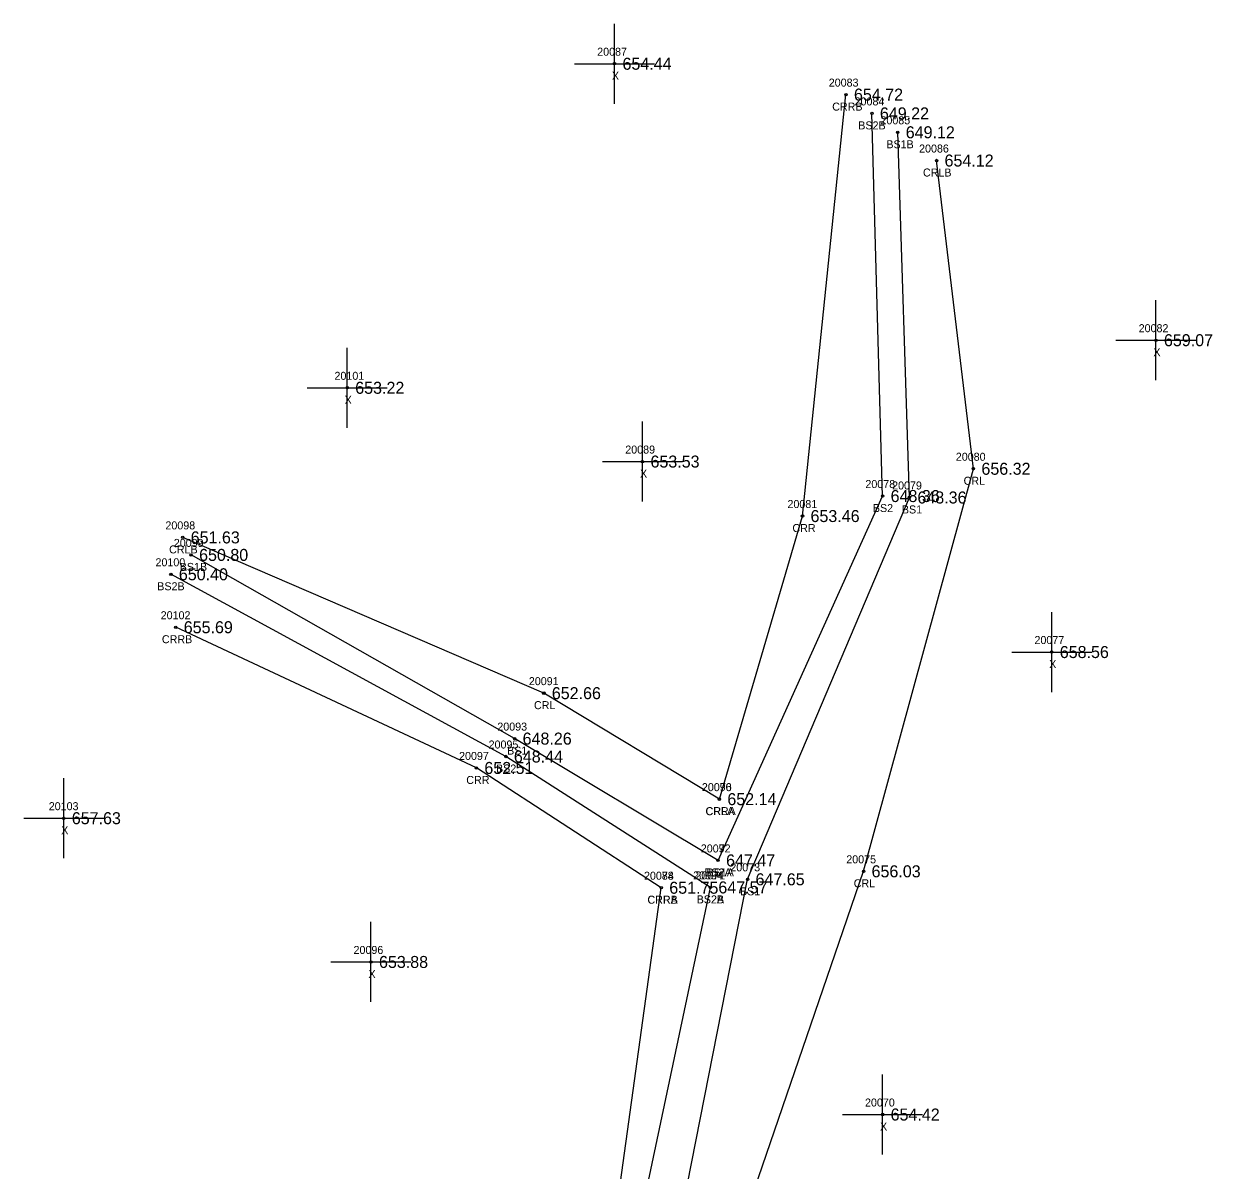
# Model space of a CAD drawing. Extents: x 1655675 to 1657082, y 1004080 to 1005193.
# Drawn here: x 1656323.4 to 1656471.9, y 1005049.5 to 1005192.8 of the extents above; entities that cross this region are included whole.
import ezdxf

# ---------------------------------------------------------------- set-up
doc = ezdxf.new("R2010")
doc.units = 0
for name, color, linetype in [('RD_DTM_BkLn2', 7, 'Continuous'), ('RD_DTM_BkLn_txCode', 7, 'Continuous'), ('RD_EX_H2O', 7, 'Continuous'), ('RD_EX_H2O_txCode', 7, 'Continuous'), ('RD_EX_Misc', 7, 'Continuous'), ('RD_EX_Misc_txCode', 7, 'Continuous'), ('RD_EX_TX_H2O_ELEV', 7, 'Continuous'), ('RD_EX_TX_Misc_ELEV', 7, 'Continuous'), ('RD_SMD_Locator', 7, 'Continuous')]:
    doc.layers.add(name, color=color, linetype=linetype)

msp = doc.modelspace()

# ---------------------------------------------------------------- linework, layer by layer
at = {"layer": 'RD_DTM_BkLn2'}
for points in [[(1656410.19, 1005088.26), (1656430.75, 1005133.81), (1656429.41, 1005181.64)], [(1656390.72, 1004627.52), (1656382.97, 1004639.34), (1656373.07, 1004660.2), (1656376.96, 1004698.66), (1656386.88, 1004718.9), (1656381.04, 1004756.9), (1656388.26, 1004792), (1656390.04, 1004832.88), (1656413.02, 1004880.46), (1656422.17, 1004937.24), (1656409.91, 1004961.28), (1656410.07, 1005007.08), (1656404.22, 1005036.82), (1656413.87, 1005085.9), (1656434.1, 1005133.63), (1656432.64, 1005179.28)], [(1656410.19, 1005088.26), (1656384.76, 1005103.49), (1656344.33, 1005126.45)], [(1656409.22, 1005084.89), (1656383.67, 1005101.25), (1656341.8, 1005124.03)], [(1656378.15, 1004634.61), (1656371.17, 1004659.81), (1656372.69, 1004701.15), (1656384.23, 1004720.35), (1656377.68, 1004756.93), (1656385.56, 1004794.36), (1656385.16, 1004833.8), (1656408.06, 1004879.84), (1656418.86, 1004937.52), (1656406.15, 1004960.8), (1656407.08, 1005007.2), (1656399.18, 1005037.18), (1656409.22, 1005084.89)]]:
    msp.add_lwpolyline(points, dxfattribs=at)
at = {"layer": 'RD_EX_H2O'}
for points in [[(1656410.35, 1005095.92), (1656420.74, 1005131.31), (1656426.17, 1005183.99)], [(1656396.09, 1004633.07), (1656383.79, 1004647.24), (1656376.78, 1004660.97), (1656381.31, 1004695.03), (1656390.77, 1004716.64), (1656386.6, 1004756.66), (1656392.47, 1004790.44), (1656395.46, 1004834.73), (1656418.17, 1004880.53), (1656428.48, 1004936.46), (1656416.99, 1004968.14), (1656420.24, 1005011.82), (1656412.2, 1005039.74), (1656428.37, 1005086.9), (1656442.1, 1005137.22), (1656437.49, 1005175.75)], [(1656410.35, 1005095.92), (1656388.41, 1005109.17), (1656343.28, 1005128.64)], [(1656403.09, 1005084.85), (1656379.98, 1005099.82), (1656342.41, 1005117.41)], [(1656368.16, 1004641.29), (1656363.88, 1004666), (1656364.85, 1004699.99), (1656373.08, 1004726.71), (1656370.55, 1004754.49), (1656376.9, 1004793.18), (1656381.94, 1004832.3), (1656396.67, 1004890.43), (1656408.46, 1004936.92), (1656401.87, 1004961.79), (1656402.89, 1005007.98), (1656396.57, 1005037.78), (1656403.09, 1005084.85)]]:
    msp.add_lwpolyline(points, dxfattribs=at)
at = {"layer": 'RD_EX_Misc'}
for p, q in [((1656397.24, 1005182.85), (1656397.24, 1005192.85)), ((1656392.24, 1005187.85), (1656402.24, 1005187.85)), ((1656464.91, 1005148.29), (1656464.91, 1005158.29)), ((1656363.84, 1005142.34), (1656363.84, 1005152.34)), ((1656459.91, 1005153.29), (1656469.91, 1005153.29)), ((1656358.84, 1005147.34), (1656368.84, 1005147.34)), ((1656400.74, 1005133.12), (1656400.74, 1005143.12)), ((1656395.74, 1005138.12), (1656405.74, 1005138.12)), ((1656451.89, 1005109.31), (1656451.89, 1005119.31)), ((1656446.89, 1005114.31), (1656456.89, 1005114.31)), ((1656328.42, 1005088.54), (1656328.42, 1005098.54)), ((1656323.42, 1005093.54), (1656333.42, 1005093.54)), ((1656366.81, 1005070.57), (1656366.81, 1005080.57)), ((1656361.81, 1005075.57), (1656371.81, 1005075.57)), ((1656430.75, 1005051.5), (1656430.75, 1005061.5)), ((1656425.75, 1005056.5), (1656435.75, 1005056.5))]:
    msp.add_line(p, q, dxfattribs=at)
at = {"layer": 'RD_SMD_Locator'}
for centre in [(1656397.24, 1005187.85), (1656426.17, 1005183.99), (1656429.41, 1005181.64), (1656432.64, 1005179.28), (1656437.49, 1005175.75), (1656464.91, 1005153.29), (1656363.84, 1005147.34), (1656400.74, 1005138.12), (1656442.1, 1005137.22), (1656430.75, 1005133.81), (1656434.1, 1005133.63), (1656420.74, 1005131.31), (1656343.28, 1005128.64), (1656344.33, 1005126.45), (1656341.8, 1005124.03), (1656342.41, 1005117.41), (1656451.89, 1005114.31), (1656388.41, 1005109.17), (1656384.76, 1005103.49), (1656383.67, 1005101.25), (1656379.98, 1005099.82), (1656410.35, 1005095.92), (1656410.35, 1005095.92), (1656328.42, 1005093.54), (1656410.19, 1005088.26), (1656410.19, 1005088.26), (1656428.37, 1005086.9), (1656413.87, 1005085.9), (1656403.09, 1005084.85), (1656403.09, 1005084.85), (1656409.22, 1005084.89), (1656409.22, 1005084.89), (1656366.81, 1005075.57), (1656430.75, 1005056.5)]:
    msp.add_circle(centre, 0.15, dxfattribs=at)

# ---------------------------------------------------------------- texts
at = {"layer": 'RD_DTM_BkLn_txCode'}
for s, p in [('20084', (1656427.25, 1005182.64)), ('BS2B', (1656427.71, 1005179.64)), ('20085', (1656430.48, 1005180.28)), ('BS1B', (1656431.22, 1005177.28)), ('20078', (1656428.6, 1005134.81)), ('20079', (1656431.94, 1005134.63)), ('BS2', (1656429.53, 1005131.81)), ('BS1', (1656433.16, 1005131.63)), ('20099', (1656342.17, 1005127.45)), ('20100', (1656339.88, 1005125.03)), ('BS1B', (1656342.91, 1005124.45)), ('BS2B', (1656340.1, 1005122.03)), ('20093', (1656382.6, 1005104.49)), ('20095', (1656381.51, 1005102.25)), ('BS1', (1656383.82, 1005101.49)), ('BS2', (1656382.44, 1005099.25)), ('20072', (1656408.03, 1005089.26)), ('20092', (1656408.03, 1005089.26)), ('20094', (1656407.07, 1005085.89)), ('20071', (1656407.35, 1005085.89)), ('BS2A', (1656408.47, 1005086.26)), ('BS1A', (1656408.75, 1005086.26)), ('20073', (1656411.72, 1005086.9)), ('BS2A', (1656407.51, 1005082.89)), ('BS2B', (1656407.52, 1005082.89)), ('BS1', (1656412.93, 1005083.9))]:
    msp.add_text(s, height=1, dxfattribs=at).set_placement(p)
at = {"layer": 'RD_EX_H2O_txCode'}
for s, p in [('20083', (1656424.02, 1005184.99)), ('CRRB', (1656424.45, 1005181.99)), ('20086', (1656435.31, 1005176.75)), ('CRLB', (1656435.79, 1005173.75)), ('20080', (1656439.9, 1005138.22)), ('CRL', (1656440.87, 1005135.22)), ('20081', (1656418.86, 1005132.31)), ('20098', (1656341.12, 1005129.64)), ('CRR', (1656419.48, 1005129.31)), ('CRLB', (1656341.58, 1005126.64)), ('20102', (1656340.53, 1005118.41)), ('CRRB', (1656340.68, 1005115.41)), ('20091', (1656386.54, 1005110.17)), ('CRL', (1656387.18, 1005107.17)), ('20097', (1656377.82, 1005100.82)), ('CRR', (1656378.72, 1005097.82)), ('20090', (1656408.16, 1005096.92)), ('20076', (1656408.17, 1005096.92)), ('CRRA', (1656408.61, 1005093.92)), ('CRLA', (1656408.64, 1005093.92)), ('20075', (1656426.21, 1005087.9)), ('20074', (1656400.93, 1005085.85)), ('20088', (1656400.93, 1005085.85)), ('CRL', (1656427.14, 1005084.9)), ('CRRA', (1656401.35, 1005082.85)), ('CRRB', (1656401.37, 1005082.85))]:
    msp.add_text(s, height=1, dxfattribs=at).set_placement(p)
at = {"layer": 'RD_EX_Misc_txCode'}
for s, p in [('20087', (1656395.08, 1005188.85)), ('X', (1656396.92, 1005185.85)), ('20082', (1656462.75, 1005154.29)), ('X', (1656464.59, 1005151.29)), ('20101', (1656362.25, 1005148.34)), ('X', (1656363.52, 1005145.34)), ('20089', (1656398.59, 1005139.12)), ('X', (1656400.43, 1005136.12)), ('20077', (1656449.73, 1005115.31)), ('X', (1656451.57, 1005112.31)), ('20103', (1656326.54, 1005094.54)), ('X', (1656328.1, 1005091.54)), ('20096', (1656364.63, 1005076.57)), ('X', (1656366.5, 1005073.57)), ('20070', (1656428.55, 1005057.5)), ('X', (1656430.43, 1005054.5))]:
    msp.add_text(s, height=1, dxfattribs=at).set_placement(p)
at = {"layer": 'RD_EX_TX_H2O_ELEV'}
for s, p in [('654.72', (1656427.17, 1005183.24)), ('654.12', (1656438.49, 1005175)), ('656.32', (1656443.1, 1005136.47)), ('653.46', (1656421.74, 1005130.56)), ('651.63', (1656344.28, 1005127.89)), ('655.69', (1656343.41, 1005116.66)), ('652.66', (1656389.41, 1005108.42)), ('652.51', (1656380.98, 1005099.07)), ('652.14', (1656411.35, 1005095.17)), ('652.14', (1656411.35, 1005095.17)), ('656.03', (1656429.37, 1005086.15)), ('651.75', (1656404.09, 1005084.1)), ('651.75', (1656404.09, 1005084.1))]:
    msp.add_text(s, height=1.5, dxfattribs=at).set_placement(p)
at = {"layer": 'RD_EX_TX_Misc_ELEV'}
for s, p in [('654.44', (1656398.24, 1005187.1)), ('649.22', (1656430.41, 1005180.89)), ('649.12', (1656433.64, 1005178.53)), ('659.07', (1656465.91, 1005152.54)), ('653.22', (1656364.84, 1005146.59)), ('653.53', (1656401.74, 1005137.37)), ('648.36', (1656431.75, 1005133.06)), ('648.36', (1656435.1, 1005132.88)), ('650.80', (1656345.33, 1005125.7)), ('650.40', (1656342.8, 1005123.28)), ('658.56', (1656452.89, 1005113.56)), ('648.26', (1656385.76, 1005102.74)), ('648.44', (1656384.67, 1005100.5)), ('657.63', (1656329.42, 1005092.79)), ('647.47', (1656411.19, 1005087.51)), ('647.47', (1656411.19, 1005087.51)), ('647.57', (1656410.22, 1005084.14)), ('647.57', (1656410.22, 1005084.14)), ('647.65', (1656414.87, 1005085.15)), ('653.88', (1656367.81, 1005074.82)), ('654.42', (1656431.75, 1005055.75))]:
    msp.add_text(s, height=1.5, dxfattribs=at).set_placement(p)

doc.saveas('drawing.dxf')
